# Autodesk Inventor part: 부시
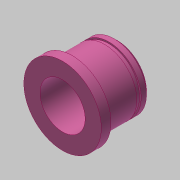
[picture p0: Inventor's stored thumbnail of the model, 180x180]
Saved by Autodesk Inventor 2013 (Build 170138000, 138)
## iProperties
Created: 2019-01
Part Number: 부시
Material: 강철, 연강
Document SubType Name: Modeling
Designer: mduedu
Density: 1 g/cm^3
Author: mduedu
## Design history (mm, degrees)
sketch "스케치1"
  geometry: L1 (0, 0)-(3, 0); L2 (3, 0)-(3, 12); L3 (3, 12)-(0, 12); L4 (0, 12)-(0, 0); L5 (3, 0)-(17, 0); L6 (17, 0)-(17, 10); L7 (17, 10)-(3, 10); L8 (3, 10)-(3, 0)
  constraints: 16 end point, 4 parallel, 2 horizontal, 2 perpendicular
  dimensions: "d0" = 17 distance between parallel lines of L6 L4; "d2" = 3 distance of L2.end L3.end; "d3" = 24 diameter of L3 L1; "d4" = 20 diameter of L7 L5
revolve "회전1" sketch "스케치1" stored, may be unused: angle "d5" = 90 deg
sketch "스케치2"
  geometry: C1 r 7 at (0, 0); 1 further point
  constraints: 1 centre point, 1 coincident
  dimensions: "d6" = 14 diameter of C1
extrude "돌출1" cut sketch "스케치2" stored distance "d7" = 10; taper "d8" = 0 deg
chamfer "모따기1" distance "d9" = 1; stored, may be unused: second distance "d10" = 2, angle "d11" = 45 deg
node "작업 평면1"
sketch "스케치3"
  geometry: C1 r 9.5 at (0, 0); C2 r 10 at (0, 0) reference; 1 further point
  constraints: 1 centre point, 1 coincident
  dimensions: "d13" = 19 diameter of C1
extrude "돌출2" cut sketch "스케치3" distance "d14" = 1.35; taper "d15" = 0 deg
node "솔리드1"
